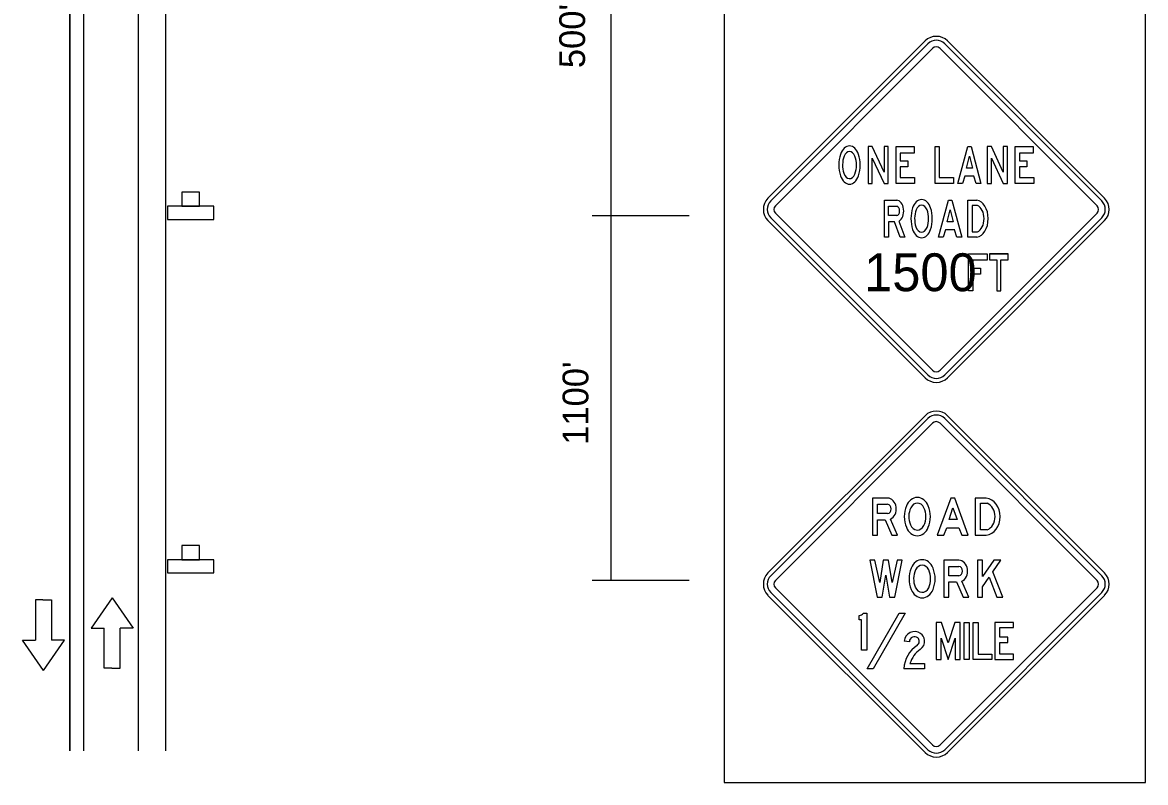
# Model space of a CAD drawing. Extents: x 21.7 to 29.1, y 5.9 to 16.2.
# Drawn here: x 24.782 to 27.394, y 7.666 to 9.433 of the extents above; entities that cross this region are included whole.
import ezdxf

# ---------------------------------------------------------------- set-up
doc = ezdxf.new("R2010")
doc.units = 0
for name, color, linetype in [('C-SIGN-FACE-N', 7, 'Continuous'), ('DETL-DIMS', 7, 'Continuous'), ('DETL-LINE', 7, 'Continuous'), ('DETL-NOTE', 7, 'Continuous'), ('USER-BORD', 7, 'Continuous')]:
    doc.layers.add(name, color=color, linetype=linetype)

# ---------------------------------------------------------------- blocks, each defined once
blk = doc.blocks.new('DIR')
at = {"layer": 'USER-BORD'}
for p, q in [((0, 0.0001), (-0.0034, -0.0048)), ((0, 0.0001), (0.0034, -0.0048)), ((-0.0034, -0.0048), (-0.0013, -0.0048)), ((-0.0013, -0.0113), (-0.0013, -0.0048)), ((0.0034, -0.0048), (0.0013, -0.0048)), ((0.0013, -0.0113), (0.0013, -0.0048)), ((-0.0001, -0.0113), (-0.0013, -0.0113)), ((-0.0001, -0.0113), (0.0001, -0.0113)), ((0.0001, -0.0113), (0.0013, -0.0113))]:
    blk.add_line(p, q, dxfattribs=at)

msp = doc.modelspace()

# ---------------------------------------------------------------- linework, layer by layer
at = {"layer": 'C-SIGN-FACE-N'}
for p, q in [((26.8817, 9.3902), (26.5163, 9.0248)), ((27.2992, 9.0248), (26.9339, 9.3902)), ((26.7587, 9.1448), (26.749, 9.1448)), ((26.749, 9.1448), (26.749, 9.0587)), ((26.7864, 9.0856), (26.7587, 9.1448)), ((26.7961, 9.1448), (26.7864, 9.1448)), ((26.7864, 9.1448), (26.7864, 9.0856)), ((26.7961, 9.0587), (26.7961, 9.1448)), ((26.8142, 9.1448), (26.856, 9.1448)), ((26.8142, 9.0587), (26.8142, 9.1448)), ((26.856, 9.1448), (26.856, 9.1295)), ((26.905, 9.1448), (26.9144, 9.1448)), ((26.905, 9.0587), (26.905, 9.1448)), ((26.9144, 9.1448), (26.9144, 9.0727)), ((27.0359, 9.1448), (27.0262, 9.1448)), ((27.0262, 9.1448), (27.0262, 9.0587)), ((27.0636, 9.0856), (27.0359, 9.1448)), ((27.0733, 9.1448), (27.0636, 9.1448)), ((27.0636, 9.1448), (27.0636, 9.0856)), ((27.0733, 9.0587), (27.0733, 9.1448)), ((27.0914, 9.1448), (27.1332, 9.1448)), ((27.0914, 9.0587), (27.0914, 9.1448)), ((27.1332, 9.1448), (27.1332, 9.1295)), ((26.7587, 9.0587), (26.7587, 9.1179)), ((26.7587, 9.1179), (26.7864, 9.0587)), ((26.856, 9.1295), (26.8237, 9.1295)), ((26.8237, 9.1295), (26.8237, 9.1118)), ((26.9782, 9.0946), (26.9848, 9.1221)), ((26.9848, 9.1221), (26.9921, 9.0946)), ((27.0359, 9.0587), (27.0359, 9.1179)), ((27.0359, 9.1179), (27.0636, 9.0587)), ((27.1332, 9.1295), (27.1009, 9.1295)), ((27.1009, 9.1295), (27.1009, 9.1118)), ((26.8237, 9.1118), (26.8415, 9.1118)), ((26.8415, 9.0975), (26.824, 9.0975)), ((26.824, 9.0975), (26.824, 9.073)), ((26.8415, 9.1118), (26.8415, 9.0975)), ((26.9921, 9.0946), (26.9782, 9.0946)), ((27.1009, 9.1118), (27.1187, 9.1118)), ((27.1187, 9.0975), (27.1012, 9.0975)), ((27.1012, 9.0975), (27.1012, 9.073)), ((27.1187, 9.1118), (27.1187, 9.0975)), ((26.824, 9.073), (26.8573, 9.073)), ((26.8573, 9.073), (26.8573, 9.0587)), ((26.9144, 9.0727), (26.9481, 9.0727)), ((26.9481, 9.0727), (26.9481, 9.0587)), ((26.9952, 9.076), (26.9953, 9.076)), ((26.9952, 9.076), (26.9953, 9.076)), ((27.1012, 9.073), (27.1345, 9.073)), ((27.1345, 9.073), (27.1345, 9.0587)), ((26.749, 9.0587), (26.7587, 9.0587)), ((26.7864, 9.0587), (26.7961, 9.0587)), ((26.8573, 9.0587), (26.8142, 9.0587)), ((26.9481, 9.0587), (26.905, 9.0587)), ((27.0262, 9.0587), (27.0359, 9.0587)), ((27.0636, 9.0587), (27.0733, 9.0587)), ((27.1345, 9.0587), (27.0914, 9.0587)), ((26.9334, 8.97), (26.94, 8.9975)), ((26.94, 8.9975), (26.9473, 8.97)), ((26.8817, 8.6073), (26.5163, 8.9726)), ((26.9473, 8.97), (26.9334, 8.97)), ((27.2992, 8.9726), (26.9339, 8.6073)), ((26.9504, 8.9514), (26.9505, 8.9514)), ((26.9504, 8.9514), (26.9505, 8.9514)), ((26.9827, 8.8957), (27.0257, 8.8957)), ((26.9827, 8.8096), (26.9827, 8.8957)), ((27.0257, 8.8957), (27.0257, 8.881)), ((27.0316, 8.8957), (27.0746, 8.8957)), ((27.0746, 8.8957), (27.0316, 8.8957)), ((27.0746, 8.8957), (27.0316, 8.8957)), ((27.0316, 8.8957), (27.0316, 8.8813)), ((27.0746, 8.8813), (27.0746, 8.8957)), ((27.0257, 8.881), (26.9926, 8.881)), ((26.9926, 8.881), (26.9926, 8.862)), ((26.9926, 8.862), (27.0105, 8.862)), ((27.0105, 8.862), (27.0105, 8.8479)), ((27.0316, 8.8813), (27.0483, 8.8813)), ((27.0483, 8.8813), (27.0483, 8.8096)), ((27.0579, 8.8096), (27.0579, 8.8813)), ((27.0579, 8.8813), (27.0746, 8.8813)), ((27.0105, 8.8479), (26.9926, 8.8479)), ((26.9926, 8.8479), (26.9926, 8.8096)), ((26.9926, 8.8096), (26.9827, 8.8096)), ((27.0483, 8.8096), (27.0579, 8.8096)), ((26.8817, 8.5192), (26.5163, 8.1538)), ((27.2992, 8.1538), (26.9339, 8.5192)), ((26.9603, 8.1472), (26.9603, 8.1472)), ((26.8817, 7.7363), (26.5163, 8.1016)), ((27.2992, 8.1016), (26.9339, 7.7363)), ((26.7285, 8.0445), (26.7285, 8.0544)), ((26.7285, 8.0445), (26.7285, 8.0544)), ((26.7285, 8.0445), (26.7285, 8.0544)), ((26.8451, 7.9938), (26.8331, 7.9949)), ((26.8451, 7.9938), (26.8331, 7.9949)), ((26.8451, 7.9938), (26.8331, 7.9949)), ((26.8451, 7.9938), (26.8451, 7.9938)), ((26.8451, 7.9938), (26.8451, 7.9938)), ((26.8451, 7.9938), (26.8451, 7.9938)), ((26.9274, 7.7428), (26.9428, 7.7583))]:
    msp.add_line(p, q, dxfattribs=at)
for points in [[(26.8882, 9.3836), (26.5229, 9.0183)], [(27.2927, 9.0183), (26.9274, 9.3836)], [(26.5337, 9.0074), (26.8991, 9.3728)], [(26.9165, 9.3728), (27.2818, 9.0074)], [(26.9953, 9.076), (26.9743, 9.076), (26.969, 9.0587), (26.9579, 9.0587), (26.981, 9.1448), (26.9885, 9.1448), (27.0117, 9.0587), (27.0006, 9.0587), (26.9952, 9.076)], [(26.7871, 8.9341), (26.7871, 9.0202), (26.7966, 9.0202), (26.8156, 9.0202)], [(26.9505, 8.9514), (26.9295, 8.9514), (26.9241, 8.9341), (26.913, 8.9341), (26.9362, 9.0202), (26.9437, 9.0202), (26.9669, 8.9341), (26.9558, 8.9341), (26.9504, 8.9514)], [(27.0023, 8.9341), (26.9814, 8.9341), (26.9814, 9.0202), (27.0023, 9.0202)], [(26.8991, 8.6247), (26.5337, 8.99)], [(26.8156, 8.9843), (26.7966, 8.9843), (26.7966, 9.0059), (26.8156, 9.0059)], [(27.2818, 8.99), (26.9165, 8.6247)], [(27.0038, 9.008), (26.9911, 9.008), (26.9911, 8.9463), (27.0038, 8.9463)], [(26.5229, 8.9791), (26.8882, 8.6138)], [(26.821, 8.9715), (26.8342, 8.9343), (26.8235, 8.9343), (26.8109, 8.97), (26.7966, 8.97), (26.7966, 8.9341), (26.7871, 8.9341)], [(26.9274, 8.6138), (27.2927, 8.9791)], [(26.8882, 8.5127), (26.5229, 8.1473)], [(26.5337, 8.1364), (26.8991, 8.5018)], [(26.9165, 8.5018), (27.2818, 8.1364)], [(27.2927, 8.1473), (26.9274, 8.5127)], [(26.7944, 8.3276), (26.7711, 8.3276), (26.7594, 8.3276), (26.7594, 8.2415)], [(26.7944, 8.2917), (26.7711, 8.2917), (26.7711, 8.3133), (26.7944, 8.3133)], [(26.9601, 8.2589), (26.9673, 8.2415), (26.9822, 8.2415), (26.9511, 8.3276), (26.9412, 8.3276), (26.9101, 8.2415), (26.925, 8.2415)], [(27.024, 8.3276), (26.9984, 8.3276), (26.9984, 8.2415)], [(27.0102, 8.2537), (27.0102, 8.3155), (27.0258, 8.3155)], [(26.7594, 8.2415), (26.7711, 8.2415), (26.7711, 8.2774), (26.7886, 8.2774), (26.8041, 8.2417)], [(26.8041, 8.2417), (26.8172, 8.2417), (26.8011, 8.2789)], [(26.925, 8.2415), (26.9322, 8.2589), (26.9601, 8.2589)], [(26.9984, 8.2415), (27.024, 8.2415)], [(27.0258, 8.2537), (27.0102, 8.2537)], [(26.9604, 8.1831), (26.937, 8.1831), (26.9253, 8.1831), (26.9253, 8.097)], [(26.9603, 8.1472), (26.937, 8.1472), (26.937, 8.1687), (26.9604, 8.1687)], [(26.9253, 8.097), (26.937, 8.097), (26.937, 8.1328), (26.9545, 8.1328), (26.97, 8.0971), (26.9831, 8.0971), (26.967, 8.1343)], [(26.5229, 8.1082), (26.8882, 7.7428)], [(26.8991, 7.7537), (26.5337, 8.119)], [(27.2818, 8.119), (26.9165, 7.7537)], [(26.9428, 7.7583), (27.2927, 8.1082)], [(26.7383, 8.0601), (26.7461, 8.0601), (26.7461, 7.974), (26.7341, 7.974), (26.7341, 8.0445), (26.7285, 8.0445)], [(26.7383, 8.0601), (26.7461, 8.0601), (26.7461, 7.974), (26.7341, 7.974), (26.7341, 8.0445), (26.7285, 8.0445)], [(26.7383, 8.0601), (26.7461, 8.0601), (26.7461, 7.974), (26.7341, 7.974), (26.7341, 8.0445), (26.7285, 8.0445)], [(26.8464, 7.943), (26.8802, 7.943), (26.8802, 7.9309), (26.8324, 7.9309)], [(26.8464, 7.943), (26.8802, 7.943), (26.8802, 7.9309), (26.8324, 7.9309)], [(26.8464, 7.943), (26.8802, 7.943), (26.8802, 7.9309), (26.8324, 7.9309)], [(26.9274, 7.7428), (26.9428, 7.7583)]]:
    msp.add_lwpolyline(points, dxfattribs=at)
for points in [[(26.956, 8.2775), (26.9374, 8.2775), (26.9462, 8.3049)], [(26.8284, 8.1831), (26.8166, 8.1831), (26.8052, 8.1315), (26.7969, 8.1831), (26.7845, 8.1831), (26.7761, 8.1315), (26.7648, 8.1831), (26.753, 8.1831), (26.7702, 8.097), (26.782, 8.097), (26.7907, 8.1486), (26.7993, 8.097), (26.8112, 8.097)], [(27.0033, 8.097), (27.0152, 8.097), (27.0152, 8.1217), (27.0305, 8.1437), (27.0489, 8.097), (27.0626, 8.097), (27.0392, 8.1562), (27.058, 8.1831), (27.0416, 8.1831), (27.0152, 8.1454), (27.0152, 8.1831), (27.0033, 8.1831)], [(26.8215, 8.0601), (26.8355, 8.0601), (26.7609, 7.9309), (26.747, 7.9309)], [(26.8215, 8.0601), (26.8355, 8.0601), (26.7609, 7.9309), (26.747, 7.9309)], [(26.8215, 8.0601), (26.8355, 8.0601), (26.7609, 7.9309), (26.747, 7.9309)], [(26.9353, 7.9524), (26.9514, 8.002), (26.9514, 7.9524), (26.9633, 7.9524), (26.9633, 8.0385), (26.9508, 8.0385), (26.9353, 7.9909), (26.9198, 8.0385), (26.9073, 8.0385), (26.9073, 7.9524), (26.9192, 7.9524), (26.9192, 8.002)], [(26.9353, 7.9524), (26.9514, 8.002), (26.9514, 7.9524), (26.9633, 7.9524), (26.9633, 8.0385), (26.9508, 8.0385), (26.9353, 7.9909), (26.9198, 8.0385), (26.9073, 8.0385), (26.9073, 7.9524), (26.9192, 7.9524), (26.9192, 8.002)], [(26.9353, 7.9524), (26.9514, 8.002), (26.9514, 7.9524), (26.9633, 7.9524), (26.9633, 8.0385), (26.9508, 8.0385), (26.9353, 7.9909), (26.9198, 8.0385), (26.9073, 8.0385), (26.9073, 7.9524), (26.9192, 7.9524), (26.9192, 8.002)], [(26.9724, 8.0385), (26.9843, 8.0385), (26.9843, 7.9524), (26.9724, 7.9524)], [(26.9724, 8.0385), (26.9843, 8.0385), (26.9843, 7.9524), (26.9724, 7.9524)], [(26.9724, 8.0385), (26.9843, 8.0385), (26.9843, 7.9524), (26.9724, 7.9524)], [(26.9934, 8.0385), (27.0053, 8.0385), (27.0053, 7.9645), (27.0366, 7.9645), (27.0366, 7.9524), (26.9934, 7.9524)], [(26.9934, 8.0385), (27.0053, 8.0385), (27.0053, 7.9645), (27.0366, 7.9645), (27.0366, 7.9524), (26.9934, 7.9524)], [(26.9934, 8.0385), (27.0053, 8.0385), (27.0053, 7.9645), (27.0366, 7.9645), (27.0366, 7.9524), (26.9934, 7.9524)], [(27.0557, 7.9645), (27.0557, 7.992), (27.0743, 7.992), (27.0743, 8.0041), (27.0557, 8.0041), (27.0557, 8.0265), (27.0871, 8.0265), (27.0871, 8.0385), (27.0439, 8.0385), (27.0439, 7.9524), (27.0871, 7.9524), (27.0871, 7.9645)], [(27.0557, 7.9645), (27.0557, 7.992), (27.0743, 7.992), (27.0743, 8.0041), (27.0557, 8.0041), (27.0557, 8.0265), (27.0871, 8.0265), (27.0871, 8.0385), (27.0439, 8.0385), (27.0439, 7.9524), (27.0871, 7.9524), (27.0871, 7.9645)], [(27.0557, 7.9645), (27.0557, 7.992), (27.0743, 7.992), (27.0743, 8.0041), (27.0557, 8.0041), (27.0557, 8.0265), (27.0871, 8.0265), (27.0871, 8.0385), (27.0439, 8.0385), (27.0439, 7.9524), (27.0871, 7.9524), (27.0871, 7.9645)]]:
    msp.add_lwpolyline(points, close=True, dxfattribs=at)
for centre, radius, start, end in [((26.9078, 9.3641), 0.0369, 45, 135), ((26.9078, 9.3641), 0.0277, 45, 135), ((26.9078, 9.3641), 0.0123, 45, 135), ((26.5424, 8.9987), 0.0369, 135, 225), ((26.5424, 8.9987), 0.0277, 135, 225), ((27.2731, 8.9987), 0.0277, 315, 45), ((27.2731, 8.9987), 0.0369, 315, 45), ((26.5424, 8.9987), 0.0123, 135, 225), ((27.2731, 8.9987), 0.0123, 315, 45), ((26.9078, 8.6334), 0.0123, 225, 315), ((26.9078, 8.6334), 0.0369, 225, 315), ((26.9078, 8.6334), 0.0277, 225, 315), ((26.9078, 8.4931), 0.0369, 45, 135), ((26.9078, 8.4931), 0.0277, 45, 135), ((26.9078, 8.4931), 0.0123, 45, 135), ((26.5424, 8.1277), 0.0369, 135, 225), ((27.2731, 8.1277), 0.0369, 315, 45), ((26.5424, 8.1277), 0.0277, 135, 225), ((26.5424, 8.1277), 0.0123, 135, 225), ((27.2731, 8.1277), 0.0123, 315, 45), ((27.2731, 8.1277), 0.0277, 315, 45), ((26.7219, 8.077), 0.0236, 286.2525, 314.1302), ((26.7219, 8.077), 0.0236, 286.2525, 314.1302), ((26.7219, 8.077), 0.0236, 286.2525, 314.1302), ((26.8572, 7.9934), 0.0241, 54.3694, 176.4795), ((26.8572, 7.9934), 0.0241, 54.3694, 176.4795), ((26.8572, 7.9934), 0.0241, 54.3694, 176.4795), ((26.8572, 7.9934), 0.012, 51.4666, 178.1909), ((26.8572, 7.9934), 0.012, 51.4666, 178.1909), ((26.8572, 7.9934), 0.012, 51.4666, 178.1909), ((26.8565, 7.9947), 0.0116, 306.1354, 44.8873), ((26.8565, 7.9947), 0.0116, 306.1354, 44.8873), ((26.8565, 7.9947), 0.0116, 306.1354, 44.8873), ((26.8588, 7.9939), 0.0215, 302.9934, 10.0902), ((26.8588, 7.9939), 0.0215, 302.9934, 10.0902), ((26.8588, 7.9939), 0.0215, 302.9934, 10.0902), ((26.8599, 7.9965), 0.0201, 3.3316, 55.5862), ((26.8599, 7.9965), 0.0201, 3.3316, 55.5862), ((26.8599, 7.9965), 0.0201, 3.3316, 55.5862), ((26.9022, 7.9273), 0.0699, 123.8618, 177.0151), ((26.9022, 7.9273), 0.0699, 123.8618, 177.0151), ((26.9022, 7.9273), 0.0699, 123.8618, 177.0151), ((26.9073, 7.9236), 0.0639, 125.1387, 162.3655), ((26.9073, 7.9236), 0.0639, 125.1387, 162.3655), ((26.9073, 7.9236), 0.0639, 125.1387, 162.3655), ((26.9078, 7.7624), 0.0369, 225, 315), ((26.9078, 7.7624), 0.0277, 225, 315), ((26.9078, 7.7624), 0.0123, 225, 315)]:
    msp.add_arc(centre, radius, start, end, dxfattribs=at)
for centre, major_axis, ratio, start_param, end_param in [((26.706, 9.1113), (0, 0.0349), 0.667963, 5.167056, 7.399315), ((26.7178, 9.1018), (0, 0.0549), 0.667963, 1.101522, 2.04007), ((26.7178, 9.1018), (0, 0.042), 0.667963, 1.053076, 2.040122), ((26.706, 9.1113), (0, 0.0219), 0.667963, 5.251232, 7.315139), ((26.6942, 9.1018), (0, 0.042), 0.667963, 4.194619, 5.230159), ((26.6942, 9.1018), (0, 0.0549), 0.667963, 4.243115, 5.181663), ((26.706, 9.0922), (0, 0.0349), 0.667963, 2.025463, 4.257722), ((26.706, 9.0922), (0, 0.0219), 0.667963, 2.025521, 4.173604), ((26.8154, 8.9951), (0, 0.0251), 0.661997, 3.487455, 6.26934), ((26.8736, 8.9867), (0, 0.0349), 0.667963, 5.167056, 7.399315), ((26.9997, 8.9772), (0, 0.0432), 0.666086, 3.232672, 6.192106), ((26.8154, 8.9951), (0, 0.0108), 0.661997, 3.174143, 6.250635), ((26.8854, 8.9772), (0, 0.0549), 0.667963, 1.101522, 2.04007), ((26.8854, 8.9772), (0, 0.042), 0.667963, 1.053076, 2.040122), ((26.8736, 8.9867), (0, 0.0219), 0.667963, 5.251232, 7.315139), ((26.8618, 8.9772), (0, 0.042), 0.667963, 4.194619, 5.230159), ((26.8618, 8.9772), (0, 0.0549), 0.667963, 4.243115, 5.181663), ((26.9973, 8.9772), (0, 0.0324), 0.666086, 3.446507, 5.978271), ((26.8736, 8.9677), (0, 0.0349), 0.667963, 2.025463, 4.257722), ((26.8736, 8.9677), (0, 0.0219), 0.667963, 2.025521, 4.173604), ((26.7942, 8.3025), (0, 0.0251), 0.813368, 3.487455, 6.269262), ((26.7942, 8.3025), (0, 0.0108), 0.813368, 3.174143, 6.250457), ((26.878, 8.2846), (0, 0.0549), 0.812335, 1.101522, 2.04007), ((26.8637, 8.2941), (0, 0.0349), 0.812335, 5.167056, 7.399315), ((26.8637, 8.2941), (0, 0.0219), 0.812335, 5.251232, 7.315139), ((26.8493, 8.2846), (0, 0.0549), 0.812335, 4.243115, 5.181663), ((27.0208, 8.2846), (0, 0.0432), 0.818392, 3.232708, 6.192058), ((27.0179, 8.2846), (0, 0.0324), 0.818392, 3.446507, 5.978271), ((26.878, 8.2846), (0, 0.042), 0.812335, 1.053076, 2.040122), ((26.8493, 8.2846), (0, 0.042), 0.812335, 4.194619, 5.230159), ((26.8637, 8.2751), (0, 0.0349), 0.812335, 2.025463, 3.141593), ((26.8637, 8.2751), (0, 0.0219), 0.812335, 2.025521, 3.099563), ((26.8637, 8.2751), (0, 0.0219), 0.812335, 3.099563, 4.173604), ((26.8637, 8.2751), (0, 0.0349), 0.812335, 3.141593, 4.257722), ((26.8748, 8.1496), (0, 0.0349), 0.812335, 5.167056, 7.399315), ((26.9601, 8.158), (0, 0.0251), 0.813368, 3.487455, 6.268841), ((26.8891, 8.14), (0, 0.0549), 0.812335, 1.101522, 2.04007), ((26.8891, 8.14), (0, 0.042), 0.812335, 1.053076, 2.040122), ((26.8748, 8.1496), (0, 0.0219), 0.812335, 5.251232, 7.315139), ((26.8605, 8.14), (0, 0.042), 0.812335, 4.194619, 5.230159), ((26.8605, 8.14), (0, 0.0549), 0.812335, 4.243115, 5.181663), ((26.9601, 8.158), (0, 0.0108), 0.813368, 3.174143, 6.249461), ((26.8748, 8.1305), (0, 0.0349), 0.812335, 2.025463, 3.141593), ((26.8748, 8.1305), (0, 0.0219), 0.812335, 2.025521, 3.099563), ((26.8748, 8.1305), (0, 0.0219), 0.812335, 3.099563, 4.173604), ((26.8748, 8.1305), (0, 0.0349), 0.812335, 3.141593, 4.257722)]:
    msp.add_ellipse(centre, major_axis=major_axis, ratio=ratio, start_param=start_param, end_param=end_param, dxfattribs=at)
at = {"layer": 'DETL-DIMS'}
for p, q in [((26.1511, 9.8738), (26.1511, 8.9847)), ((26.107, 8.9847), (26.3328, 8.9847)), ((26.107, 8.9847), (26.107, 8.9847)), ((26.1511, 8.9847), (26.1511, 8.1372)), ((26.107, 8.1372), (26.3328, 8.1372)), ((26.107, 8.1372), (26.107, 8.1372))]:
    msp.add_line(p, q, dxfattribs=at)
at = {"layer": 'DETL-LINE'}
for p, q in [((24.8927, 7.7401), (24.8927, 15.6283)), ((24.893, 9.2959), (24.893, 15.5751)), ((24.9252, 9.2959), (24.9252, 15.5751)), ((24.9252, 7.7401), (24.9252, 15.5547)), ((26.4145, 11.5089), (26.4145, 7.6665)), ((27.3944, 7.6665), (27.3944, 11.5089)), ((25.0521, 9.2959), (25.0521, 10.8977)), ((25.1155, 9.2959), (25.1155, 10.8977)), ((24.893, 7.7401), (24.893, 9.2959)), ((24.9252, 7.7401), (24.9252, 9.2959)), ((25.0521, 7.7401), (25.0521, 9.2959)), ((25.1159, 7.7401), (25.1159, 9.2959)), ((26.4145, 7.6665), (27.3944, 7.6665))]:
    msp.add_line(p, q, dxfattribs=at)
for points in [[(25.1531, 9.0059), (25.1944, 9.0059), (25.1944, 9.0386), (25.1531, 9.0386)], [(25.1195, 9.0059), (25.1195, 8.975), (25.2277, 8.975), (25.2277, 9.0059)], [(25.1531, 8.1845), (25.1944, 8.1845), (25.1944, 8.2172), (25.1531, 8.2172)], [(25.1195, 8.1845), (25.1195, 8.1536), (25.2277, 8.1536), (25.2277, 8.1845)]]:
    msp.add_lwpolyline(points, close=True, dxfattribs=at)

# ---------------------------------------------------------------- block references
at = {"layer": 'DETL-LINE', "xscale": 14.360714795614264}
for p, yscale in [((24.8311, 7.9286), -14.360714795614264), ((24.9912, 8.0942), 14.360714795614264)]:
    msp.add_blockref('DIR', p, dxfattribs=dict(at, yscale=yscale))

# ---------------------------------------------------------------- texts
at = {"layer": 'DETL-NOTE'}
for s, p in [("500'", (26.0908, 9.3271)), ("1100'", (26.0985, 8.4515))]:
    msp.add_text(s, height=0.06, rotation=90, dxfattribs=at).set_placement(p)
msp.add_text('1500', height=0.088, dxfattribs=at).set_placement((26.7399, 8.8086))

doc.saveas('drawing.dxf')
